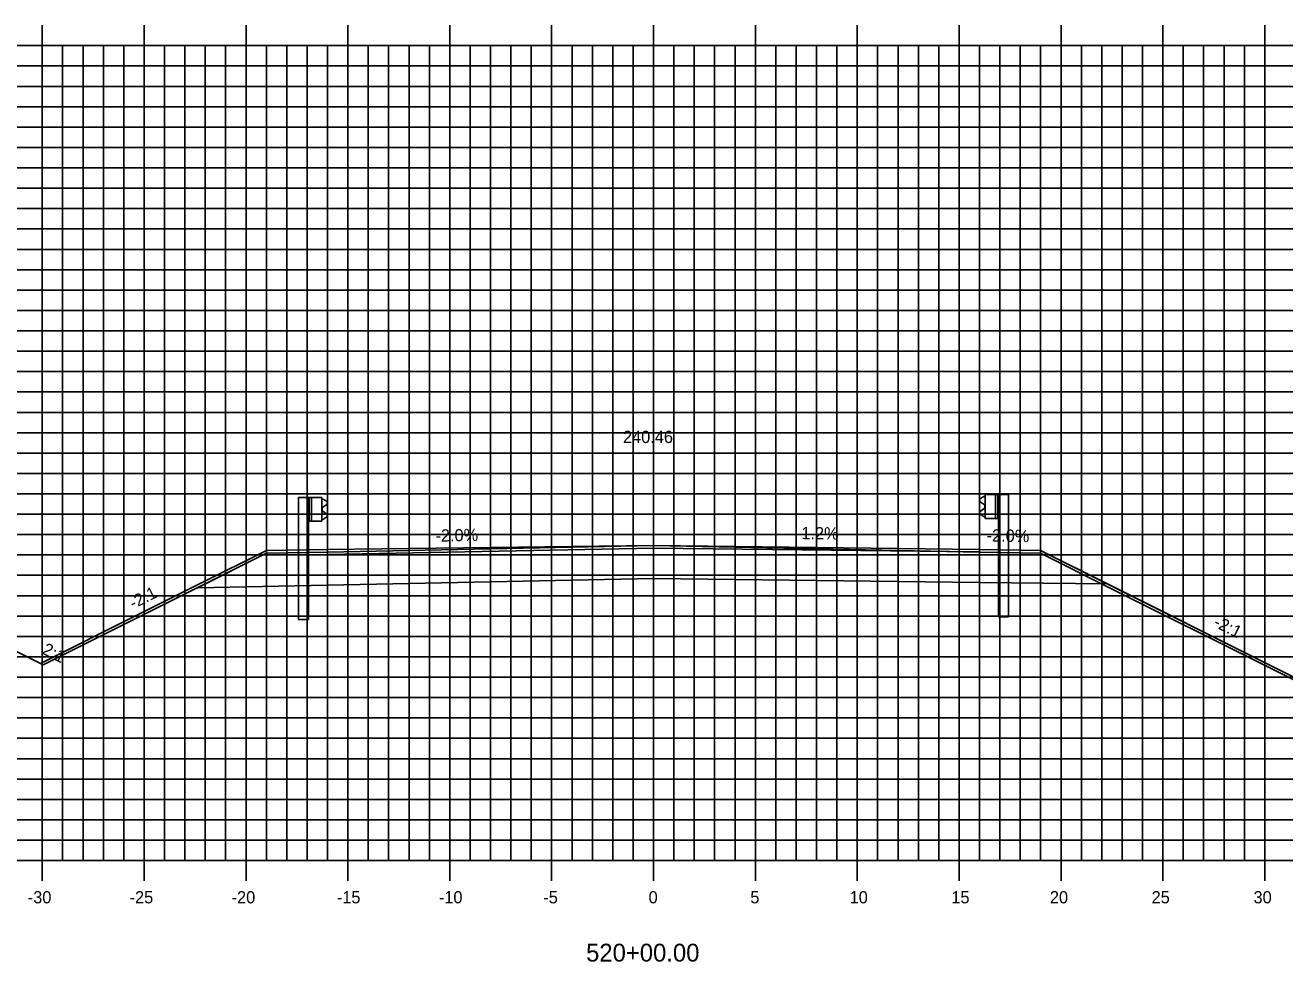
# Model space of a CAD drawing. Extents: x 1170543 to 1177585, y 609599 to 610623.
# Drawn here: x 1174587.3 to 1174649.1, y 610272.8 to 610318.8 of the extents above; entities that cross this region are included whole.
import ezdxf

# ---------------------------------------------------------------- set-up
doc = ezdxf.new("R2010")
doc.units = 0
for name, color, linetype in [('ANNOTATION', 7, 'Continuous'), ('D_Guardrail_Beam_Lt', 7, 'Continuous'), ('D_Guardrail_Beam_Rt', 7, 'Continuous'), ('D_Roadway_Centerline', 7, 'Continuous'), ('D_Roadway_Centerline_Text', 7, 'Continuous'), ('D_Roadway_Edge_Shoulder', 7, 'Continuous'), ('D_Roadway_Edge_TW', 7, 'Continuous'), ('D_Roadway_Pavement', 7, 'Continuous'), ('D_Roadway_SlopeLines', 7, 'Continuous'), ('D_Roadway_SubGrade', 7, 'Continuous'), ('H_V ANNOTATION', 7, 'Continuous'), ('MAJOR', 7, 'Continuous'), ('MINOR', 7, 'Continuous'), ('S_Roadway_Centerline', 7, 'Continuous')]:
    doc.layers.add(name, color=color, linetype=linetype)

msp = doc.modelspace()

# ---------------------------------------------------------------- linework, layer by layer
at = {"layer": 'D_Guardrail_Beam_Lt'}
for p, q in [((1174600.66, 610295.629), (1174600.66, 610289.629)), ((1174601.131, 610295.629), (1174600.66, 610295.629)), ((1174601.818, 610295.629), (1174601.131, 610295.629)), ((1174601.131, 610295.629), (1174601.131, 610294.462)), ((1174601.193, 610295.629), (1174601.193, 610294.462)), ((1174601.297, 610295.629), (1174601.297, 610294.462)), ((1174601.818, 610294.462), (1174601.818, 610295.629)), ((1174601.818, 610295.546), (1174601.892, 610295.531)), ((1174602.052, 610295.281), (1174601.856, 610295.145)), ((1174601.908, 610295.524), (1174602.052, 610295.424)), ((1174601.823, 610295.081), (1174601.823, 610295.01)), ((1174601.856, 610294.946), (1174602.052, 610294.81)), ((1174602.052, 610294.667), (1174601.908, 610294.567)), ((1174601.131, 610294.462), (1174601.818, 610294.462)), ((1174601.152, 610289.629), (1174601.152, 610294.462)), ((1174601.892, 610294.56), (1174601.818, 610294.546)), ((1174601.152, 610289.629), (1174600.66, 610289.629))]:
    msp.add_line(p, q, dxfattribs=at)
for centre, major_axis, start_param, end_param in [((1174601.884, 610295.49), (0.0417, 0), 0.959931, 1.376053), ((1174602.001, 610295.353), (0.0877, 0), 5.323254, 7.243116), ((1174601.902, 610295.081), (-0.0789, 0), 5.323254, 6.283185), ((1174601.902, 610295.01), (-0.0789, 0), 6.283185, 7.243116), ((1174602.001, 610294.738), (0.0877, 0), 5.323254, 7.243116), ((1174601.884, 610294.601), (0.0417, 0), 4.907132, 5.323254)]:
    msp.add_ellipse(centre, major_axis=major_axis, ratio=0.995501, start_param=start_param, end_param=end_param, dxfattribs=at)
at = {"layer": 'D_Guardrail_Beam_Rt'}
for p, q in [((1174634.27, 610295.657), (1174634.126, 610295.557)), ((1174634.126, 610295.414), (1174634.322, 610295.277)), ((1174634.36, 610295.678), (1174634.286, 610295.663)), ((1174634.355, 610295.213), (1174634.355, 610295.143)), ((1174634.36, 610295.761), (1174635.047, 610295.761)), ((1174634.36, 610294.595), (1174634.36, 610295.761)), ((1174634.881, 610295.761), (1174634.881, 610294.595)), ((1174634.985, 610295.761), (1174634.985, 610294.595)), ((1174635.047, 610295.761), (1174635.518, 610295.761)), ((1174635.047, 610295.761), (1174635.047, 610294.595)), ((1174635.518, 610295.761), (1174635.518, 610289.761)), ((1174634.322, 610295.079), (1174634.126, 610294.942)), ((1174634.126, 610294.799), (1174634.27, 610294.699)), ((1174634.286, 610294.693), (1174634.36, 610294.678)), ((1174635.047, 610294.595), (1174634.36, 610294.595)), ((1174635.027, 610289.761), (1174635.027, 610294.595)), ((1174635.027, 610289.761), (1174635.518, 610289.761))]:
    msp.add_line(p, q, dxfattribs=at)
for centre, major_axis, start_param, end_param in [((1174634.177, 610295.485), (-0.0877, 0), 5.323254, 7.243116), ((1174634.294, 610295.623), (-0.0417, 0), 4.907132, 5.323254), ((1174634.276, 610295.213), (0.0789, 0), 0, 0.959931), ((1174634.177, 610294.871), (-0.0877, 0), 5.323254, 7.243116), ((1174634.294, 610294.733), (-0.0417, 0), 0.959931, 1.376053), ((1174634.276, 610295.143), (0.0789, 0), 5.323254, 6.283185)]:
    msp.add_ellipse(centre, major_axis=major_axis, ratio=0.995501, start_param=start_param, end_param=end_param, dxfattribs=at)
at = {"layer": 'D_Roadway_Centerline'}
msp.add_lwpolyline([(1174588.006, 610287.477), (1174588.141, 610287.409), (1174599.089, 610292.883), (1174602.089, 610292.943), (1174618.089, 610293.263), (1174634.089, 610293.076), (1174637.089, 610293.016), (1174640.366, 610291.377), (1174648.172, 610287.474), (1174651.041, 610286.04)], dxfattribs=at)
at = {"layer": 'D_Roadway_Edge_Shoulder'}
for points in [[(1174602.089, 610292.943), (1174602.089, 610292.818)], [(1174634.089, 610293.076), (1174634.089, 610292.951)]]:
    msp.add_lwpolyline(points, dxfattribs=at)
at = {"layer": 'D_Roadway_Edge_TW'}
msp.add_lwpolyline([(1174602.089, 610292.818), (1174602.089, 610292.943), (1174618.089, 610293.263), (1174634.089, 610293.076), (1174634.089, 610292.951), (1174618.089, 610293.138)], close=True, dxfattribs=at)
at = {"layer": 'D_Roadway_Pavement'}
msp.add_lwpolyline([(1174602.089, 610292.818), (1174602.089, 610292.818), (1174618.089, 610293.138), (1174634.089, 610292.951), (1174634.089, 610292.951), (1174618.089, 610293.138)], close=True, dxfattribs=at)
for points in [[(1174602.089, 610292.818), (1174602.089, 610292.818)], [(1174602.089, 610292.818), (1174602.089, 610292.818)], [(1174634.089, 610292.951), (1174634.089, 610292.951)], [(1174634.089, 610292.951), (1174634.089, 610292.951)]]:
    msp.add_lwpolyline(points, dxfattribs=at)
at = {"layer": 'D_Roadway_SlopeLines'}
for points in [[(1174637.089, 610293.016), (1174648.172, 610287.474)], [(1174648.172, 610287.474), (1174651.041, 610286.04)]]:
    msp.add_lwpolyline(points, dxfattribs=at)
at = {"layer": 'D_Roadway_SubGrade'}
for points in [[(1174602.089, 610292.943), (1174599.089, 610292.883), (1174595.704, 610291.191), (1174602.089, 610291.318)], [(1174602.089, 610291.318), (1174602.089, 610292.818), (1174618.089, 610293.138), (1174634.089, 610292.951), (1174634.089, 610291.451), (1174618.089, 610291.638)], [(1174634.089, 610293.076), (1174637.089, 610293.016), (1174640.366, 610291.377), (1174634.089, 610291.451)]]:
    msp.add_lwpolyline(points, close=True, dxfattribs=at)
at = {"layer": 'MAJOR'}
for p, q in [((1174588.089, 610318.803), (1174588.089, 610317.801)), ((1174593.089, 610318.803), (1174593.089, 610317.801)), ((1174598.089, 610318.803), (1174598.089, 610317.801)), ((1174603.089, 610318.803), (1174603.089, 610317.801)), ((1174608.089, 610318.803), (1174608.089, 610317.801)), ((1174613.089, 610318.803), (1174613.089, 610317.801)), ((1174618.089, 610318.803), (1174618.089, 610317.801)), ((1174623.089, 610318.803), (1174623.089, 610317.801)), ((1174628.089, 610318.803), (1174628.089, 610317.801)), ((1174633.089, 610318.803), (1174633.089, 610317.801)), ((1174638.089, 610318.803), (1174638.089, 610317.801)), ((1174643.089, 610318.803), (1174643.089, 610317.801)), ((1174648.089, 610318.803), (1174648.089, 610317.801)), ((1174548.089, 610317.801), (1174688.089, 610317.801)), ((1174548.089, 610317.801), (1174688.089, 610317.801)), ((1174588.089, 610277.801), (1174588.089, 610317.801)), ((1174593.089, 610277.801), (1174593.089, 610317.801)), ((1174598.089, 610277.801), (1174598.089, 610317.801)), ((1174603.089, 610277.801), (1174603.089, 610317.801)), ((1174608.089, 610277.801), (1174608.089, 610317.801)), ((1174613.089, 610277.801), (1174613.089, 610317.801)), ((1174618.089, 610277.801), (1174618.089, 610317.801)), ((1174623.089, 610277.801), (1174623.089, 610317.801)), ((1174628.089, 610277.801), (1174628.089, 610317.801)), ((1174633.089, 610277.801), (1174633.089, 610317.801)), ((1174638.089, 610277.801), (1174638.089, 610317.801)), ((1174643.089, 610277.801), (1174643.089, 610317.801)), ((1174648.089, 610277.801), (1174648.089, 610317.801)), ((1174548.089, 610312.801), (1174688.089, 610312.801)), ((1174548.089, 610307.801), (1174688.089, 610307.801)), ((1174548.089, 610302.801), (1174688.089, 610302.801)), ((1174548.089, 610297.801), (1174688.089, 610297.801)), ((1174548.089, 610292.801), (1174688.089, 610292.801)), ((1174548.089, 610287.801), (1174688.089, 610287.801)), ((1174548.089, 610282.801), (1174688.089, 610282.801)), ((1174548.089, 610277.801), (1174688.089, 610277.801)), ((1174548.089, 610277.801), (1174688.089, 610277.801)), ((1174588.089, 610276.799), (1174588.089, 610277.801)), ((1174593.089, 610276.799), (1174593.089, 610277.801)), ((1174598.089, 610276.799), (1174598.089, 610277.801)), ((1174603.089, 610276.799), (1174603.089, 610277.801)), ((1174608.089, 610276.799), (1174608.089, 610277.801)), ((1174613.089, 610276.799), (1174613.089, 610277.801)), ((1174618.089, 610276.799), (1174618.089, 610277.801)), ((1174623.089, 610276.799), (1174623.089, 610277.801)), ((1174628.089, 610276.799), (1174628.089, 610277.801)), ((1174633.089, 610276.799), (1174633.089, 610277.801)), ((1174638.089, 610276.799), (1174638.089, 610277.801)), ((1174643.089, 610276.799), (1174643.089, 610277.801)), ((1174648.089, 610276.799), (1174648.089, 610277.801))]:
    msp.add_line(p, q, dxfattribs=at)
at = {"layer": 'MINOR'}
for p, q in [((1174589.089, 610277.801), (1174589.089, 610317.801)), ((1174590.089, 610277.801), (1174590.089, 610317.801)), ((1174591.089, 610277.801), (1174591.089, 610317.801)), ((1174592.089, 610277.801), (1174592.089, 610317.801)), ((1174594.089, 610277.801), (1174594.089, 610317.801)), ((1174595.089, 610277.801), (1174595.089, 610317.801)), ((1174596.089, 610277.801), (1174596.089, 610317.801)), ((1174597.089, 610277.801), (1174597.089, 610317.801)), ((1174599.089, 610277.801), (1174599.089, 610317.801)), ((1174600.089, 610277.801), (1174600.089, 610317.801)), ((1174601.089, 610277.801), (1174601.089, 610317.801)), ((1174602.089, 610277.801), (1174602.089, 610317.801)), ((1174604.089, 610277.801), (1174604.089, 610317.801)), ((1174605.089, 610277.801), (1174605.089, 610317.801)), ((1174606.089, 610277.801), (1174606.089, 610317.801)), ((1174607.089, 610277.801), (1174607.089, 610317.801)), ((1174609.089, 610277.801), (1174609.089, 610317.801)), ((1174610.089, 610277.801), (1174610.089, 610317.801)), ((1174611.089, 610277.801), (1174611.089, 610317.801)), ((1174612.089, 610277.801), (1174612.089, 610317.801)), ((1174614.089, 610277.801), (1174614.089, 610317.801)), ((1174615.089, 610277.801), (1174615.089, 610317.801)), ((1174616.089, 610277.801), (1174616.089, 610317.801)), ((1174617.089, 610277.801), (1174617.089, 610317.801)), ((1174619.089, 610277.801), (1174619.089, 610317.801)), ((1174620.089, 610277.801), (1174620.089, 610317.801)), ((1174621.089, 610277.801), (1174621.089, 610317.801)), ((1174622.089, 610277.801), (1174622.089, 610317.801)), ((1174624.089, 610277.801), (1174624.089, 610317.801)), ((1174625.089, 610277.801), (1174625.089, 610317.801)), ((1174626.089, 610277.801), (1174626.089, 610317.801)), ((1174627.089, 610277.801), (1174627.089, 610317.801)), ((1174629.089, 610277.801), (1174629.089, 610317.801)), ((1174630.089, 610277.801), (1174630.089, 610317.801)), ((1174631.089, 610277.801), (1174631.089, 610317.801)), ((1174632.089, 610277.801), (1174632.089, 610317.801)), ((1174634.089, 610277.801), (1174634.089, 610317.801)), ((1174635.089, 610277.801), (1174635.089, 610317.801)), ((1174636.089, 610277.801), (1174636.089, 610317.801)), ((1174637.089, 610277.801), (1174637.089, 610317.801)), ((1174639.089, 610277.801), (1174639.089, 610317.801)), ((1174640.089, 610277.801), (1174640.089, 610317.801)), ((1174641.089, 610277.801), (1174641.089, 610317.801)), ((1174642.089, 610277.801), (1174642.089, 610317.801)), ((1174644.089, 610277.801), (1174644.089, 610317.801)), ((1174645.089, 610277.801), (1174645.089, 610317.801)), ((1174646.089, 610277.801), (1174646.089, 610317.801)), ((1174647.089, 610277.801), (1174647.089, 610317.801)), ((1174548.089, 610316.801), (1174688.089, 610316.801)), ((1174548.089, 610315.801), (1174688.089, 610315.801)), ((1174548.089, 610314.801), (1174688.089, 610314.801)), ((1174548.089, 610313.801), (1174688.089, 610313.801)), ((1174548.089, 610311.801), (1174688.089, 610311.801)), ((1174548.089, 610310.801), (1174688.089, 610310.801)), ((1174548.089, 610309.801), (1174688.089, 610309.801)), ((1174548.089, 610308.801), (1174688.089, 610308.801)), ((1174548.089, 610306.801), (1174688.089, 610306.801)), ((1174548.089, 610305.801), (1174688.089, 610305.801)), ((1174548.089, 610304.801), (1174688.089, 610304.801)), ((1174548.089, 610303.801), (1174688.089, 610303.801)), ((1174548.089, 610301.801), (1174688.089, 610301.801)), ((1174548.089, 610300.801), (1174688.089, 610300.801)), ((1174548.089, 610299.801), (1174688.089, 610299.801)), ((1174548.089, 610298.801), (1174688.089, 610298.801)), ((1174548.089, 610296.801), (1174688.089, 610296.801)), ((1174548.089, 610295.801), (1174688.089, 610295.801)), ((1174548.089, 610294.801), (1174688.089, 610294.801)), ((1174548.089, 610293.801), (1174688.089, 610293.801)), ((1174548.089, 610291.801), (1174688.089, 610291.801)), ((1174548.089, 610290.801), (1174688.089, 610290.801)), ((1174548.089, 610289.801), (1174688.089, 610289.801)), ((1174548.089, 610288.801), (1174688.089, 610288.801)), ((1174548.089, 610286.801), (1174688.089, 610286.801)), ((1174548.089, 610285.801), (1174688.089, 610285.801)), ((1174548.089, 610284.801), (1174688.089, 610284.801)), ((1174548.089, 610283.801), (1174688.089, 610283.801)), ((1174548.089, 610281.801), (1174688.089, 610281.801)), ((1174548.089, 610280.801), (1174688.089, 610280.801)), ((1174548.089, 610279.801), (1174688.089, 610279.801)), ((1174548.089, 610278.801), (1174688.089, 610278.801))]:
    msp.add_line(p, q, dxfattribs=at)
at = {"layer": 'S_Roadway_Centerline'}
msp.add_lwpolyline([(1174573.331, 610294.814), (1174588.006, 610287.477), (1174592.733, 610289.84), (1174592.736, 610289.839), (1174592.736, 610289.839), (1174592.736, 610289.839), (1174592.736, 610289.839), (1174592.736, 610289.839), (1174592.736, 610289.839), (1174592.736, 610289.839), (1174592.736, 610289.839), (1174592.736, 610289.839), (1174595.812, 610291.377), (1174595.812, 610291.377), (1174599.089, 610293.016), (1174602.089, 610293.076), (1174602.089, 610293.076), (1174602.089, 610293.076), (1174618.089, 610293.263), (1174618.089, 610293.263), (1174634.089, 610292.943), (1174637.089, 610292.883), (1174637.089, 610292.883), (1174640.474, 610291.191), (1174640.474, 610291.191), (1174640.475, 610291.191), (1174648.172, 610287.342), (1174650.777, 610286.039)], dxfattribs=at)

# ---------------------------------------------------------------- texts
at = {"layer": 'ANNOTATION'}
for s, rotation, p in [('-2.0%', 1.14576, (1174607.392, 610293.45)), ('-1.2%', 359.32829, (1174625.074, 610293.581)), ('-2.0%', 358.85424, (1174634.432, 610293.469)), ('-2:1', 26.56505, (1174592.544, 610290.129)), ('-2:1', 333.43495, (1174645.527, 610289.315)), ('2:1', 333.43495, (1174588.04, 610287.978))]:
    msp.add_text(s, height=0.6, rotation=rotation, dxfattribs=at).set_placement(p)
at = {"layer": 'D_Roadway_Centerline'}
for s, p in [('C', (1174618.084, 610293.263)), ('L', (1174618.089, 610293.256))]:
    msp.add_text(s, height=0.0146, dxfattribs=at).set_placement(p)
at = {"layer": 'D_Roadway_Centerline_Text'}
msp.add_text('240.46', height=0.6, dxfattribs=at).set_placement((1174616.591, 610298.295))
msp.add_text('240.46', height=0.6, dxfattribs=at).set_placement((1174616.591, 610298.295))
at = {"layer": 'H_V ANNOTATION'}
for s, height, p in [('-30', 0.6, (1174587.377, 610275.701)), ('-25', 0.6, (1174592.374, 610275.701)), ('-20', 0.6, (1174597.383, 610275.701)), ('-15', 0.6, (1174602.546, 610275.701)), ('-10', 0.6, (1174607.554, 610275.701)), ('-5', 0.6, (1174612.68, 610275.701)), ('0', 0.6, (1174617.848, 610275.701)), ('5', 0.6, (1174622.84, 610275.701)), ('10', 0.6, (1174627.714, 610275.701)), ('15', 0.6, (1174632.706, 610275.701)), ('20', 0.6, (1174637.543, 610275.701)), ('25', 0.6, (1174642.535, 610275.701)), ('30', 0.6, (1174647.538, 610275.701)), ('520+00.00', 0.875, (1174614.78, 610272.844))]:
    msp.add_text(s, height=height, dxfattribs=at).set_placement(p)

doc.saveas('drawing.dxf')
